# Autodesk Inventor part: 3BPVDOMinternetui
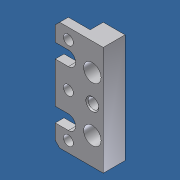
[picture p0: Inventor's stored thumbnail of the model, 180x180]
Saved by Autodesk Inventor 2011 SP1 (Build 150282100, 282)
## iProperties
Created: 2011-07
Part Number: 3BPVDOMinternetui
Document SubType Name: Modeling
Designer: Darius
Density: 1 g/cm^3
Author: Darius
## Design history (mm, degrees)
feature "Base1"
body "Solid1"
